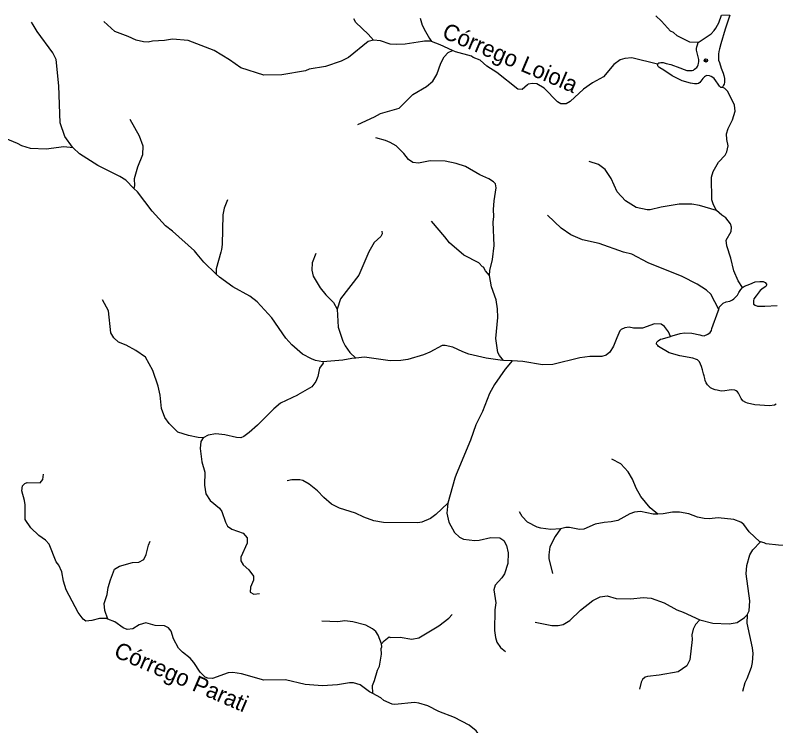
# Model space of a CAD drawing. Extents: x 317.8 to 344.1, y 7676.8 to 7704.8.
# Drawn here: x 330.394 to 334.107, y 7701.2 to 7704.671 of the extents above; entities that cross this region are included whole.
import ezdxf
from ezdxf.enums import TextEntityAlignment as Align

# ---------------------------------------------------------------- set-up
doc = ezdxf.new("R2010")
doc.units = 0
doc.header["$LTSCALE"] = 0.032
doc.header["$PDMODE"] = 32
doc.header["$PDSIZE"] = 0.016
doc.linetypes.add('SHORT_DASHED', pattern=[2.7, 1.5, -1.2])
for name, color, linetype, lineweight in [('2', 7, 'Continuous', 25), ('62', 7, 'SHORT_DASHED', 13), ('7', 7, 'Continuous', 25)]:
    doc.layers.add(name, color=color, linetype=linetype, lineweight=lineweight)
doc.layers.add('61', color=7, linetype='Continuous')

msp = doc.modelspace()

# ---------------------------------------------------------------- linework, layer by layer
at = {"layer": '2'}
for points in [[(333.7284, 7704.5377), (333.7423, 7704.5476), (333.7665, 7704.5638), (333.7907, 7704.581), (333.8053, 7704.5964), (333.8137, 7704.6085), (333.822, 7704.6227), (333.8283, 7704.6344), (333.8424, 7704.671)], [(333.8821, 7704.6714), (333.8594, 7704.6033), (333.8386, 7704.5314), (333.8311, 7704.5077), (333.8282, 7704.4945), (333.8273, 7704.4812), (333.8273, 7704.4671), (333.8273, 7704.4519), (333.8311, 7704.4406), (333.8396, 7704.4122), (333.849, 7704.3885), (333.8538, 7704.3762), (333.8556, 7704.363), (333.8566, 7704.3526), (333.8566, 7704.3441), (333.8547, 7704.3346), (333.8519, 7704.3289), (333.8468, 7704.3191)], [(333.5294, 7704.4321), (333.5308, 7704.4345), (333.5333, 7704.437), (333.5358, 7704.4387), (333.5396, 7704.4395), (333.5454, 7704.4404), (333.5567, 7704.4399), (333.5721, 7704.4362), (333.5938, 7704.4299), (333.6384, 7704.4137), (333.6601, 7704.4057), (333.6722, 7704.4016), (333.6818, 7704.4011), (333.6898, 7704.4011), (333.6981, 7704.4016), (333.7056, 7704.4036), (333.7106, 7704.4078), (333.7169, 7704.412), (333.7215, 7704.4166), (333.7252, 7704.4212), (333.7281, 7704.4287), (333.7298, 7704.4362), (333.7298, 7704.437), (333.7302, 7704.4429), (333.7302, 7704.4554), (333.7294, 7704.462), (333.724, 7704.4804), (333.7202, 7704.5004), (333.7202, 7704.5088), (333.7219, 7704.5163), (333.7252, 7704.5267), (333.7284, 7704.5377)], [(333.8468, 7704.3191), (333.8445, 7704.3181), (333.8391, 7704.3189), (333.8312, 7704.3248), (333.8249, 7704.334), (333.8141, 7704.3515), (333.8062, 7704.3623), (333.7986, 7704.3678), (333.7907, 7704.3723), (333.7828, 7704.3753), (333.7707, 7704.3761), (333.764, 7704.3744), (333.7582, 7704.3707), (333.7507, 7704.3619), (333.7407, 7704.3498), (333.7356, 7704.3431), (333.7286, 7704.3373), (333.7227, 7704.3356), (333.7156, 7704.3356), (333.7102, 7704.3365), (333.6906, 7704.3394), (333.6489, 7704.3511), (333.6013, 7704.3757), (333.56, 7704.4032), (333.5408, 7704.4137), (333.5358, 7704.4178), (333.5325, 7704.4207), (333.5316, 7704.4237), (333.5308, 7704.4274), (333.5294, 7704.4321)], [(333.9441, 7703.3415), (333.9545, 7703.3478), (333.9795, 7703.3582), (334.0066, 7703.3686), (334.0295, 7703.3707), (334.0452, 7703.3707), (334.0556, 7703.3665), (334.0618, 7703.3582), (334.0618, 7703.353), (334.0587, 7703.3457), (334.0452, 7703.3373), (334.0306, 7703.3259), (334.0108, 7703.3009), (333.9993, 7703.2863), (333.9972, 7703.2769), (333.9972, 7703.2675), (333.9983, 7703.2602), (334.0056, 7703.255), (334.017, 7703.2508), (334.0493, 7703.2508), (334.0535, 7703.2508), (334.114, 7703.2529)], [(333.8282, 7703.2344), (333.8325, 7703.2467), (333.8409, 7703.2571), (333.8502, 7703.2644), (333.8648, 7703.2706), (333.8826, 7703.2748), (333.8961, 7703.2811), (333.9024, 7703.2852), (333.9201, 7703.304), (333.9263, 7703.3175), (333.9357, 7703.3311), (333.9441, 7703.3415)], [(333.5921, 7703.1024), (333.6001, 7703.1049), (333.6397, 7703.1164), (333.6616, 7703.1195), (333.697, 7703.1174), (333.7356, 7703.1101), (333.745, 7703.107), (333.7564, 7703.1059), (333.7752, 7703.1132), (333.7867, 7703.1216), (333.7929, 7703.131), (333.794, 7703.1403), (333.8252, 7703.2258), (333.8282, 7703.2344)], [(334.1077, 7702.7714), (334.1004, 7702.7672), (334.0754, 7702.763), (334.0045, 7702.7682), (333.9691, 7702.7755), (333.9607, 7702.7797), (333.9461, 7702.788), (333.9378, 7702.7995), (333.9284, 7702.8193), (333.9253, 7702.8245), (333.9201, 7702.8318), (333.9138, 7702.837), (333.9065, 7702.8401), (333.8919, 7702.8412), (333.8784, 7702.8401), (333.8575, 7702.836), (333.8398, 7702.8349), (333.8211, 7702.8391), (333.8106, 7702.8422), (333.7981, 7702.8464), (333.7887, 7702.8516), (333.7783, 7702.861), (333.7731, 7702.8662), (333.7669, 7702.8756), (333.7616, 7702.8871), (333.7606, 7702.8964), (333.7575, 7702.91), (333.7543, 7702.9194), (333.7491, 7702.9392), (333.7439, 7702.9548), (333.7387, 7702.9663), (333.7335, 7702.9777), (333.7304, 7702.9819), (333.7252, 7702.9882), (333.72, 7702.9902), (333.7022, 7702.9955), (333.6387, 7703.0069), (333.5865, 7703.0215), (333.5344, 7703.0528), (333.5302, 7703.058), (333.5271, 7703.0611), (333.525, 7703.0642), (333.525, 7703.0684), (333.5261, 7703.0736), (333.5323, 7703.0809), (333.5438, 7703.0882), (333.5532, 7703.0903), (333.5921, 7703.1024)]]:
    msp.add_lwpolyline(points, dxfattribs=at)
msp.add_point((333.7653, 7704.4505), dxfattribs=at)
at = {"layer": '62'}
msp.add_line((333.8424, 7704.671), (333.8821, 7704.6714), dxfattribs=at)
at = {"layer": '7'}
msp.add_line((332.8198, 7702.9823), (332.7774, 7702.9849), dxfattribs=at)
for points in [[(333.7284, 7704.5377), (333.6871, 7704.539), (333.626, 7704.5709), (333.6074, 7704.5875), (333.5927, 7704.5935), (333.5487, 7704.6429), (333.5207, 7704.6678)], [(330.677, 7704.0232), (330.6729, 7704.0272), (330.6365, 7704.0793), (330.6128, 7704.145), (330.6059, 7704.3271), (330.5942, 7704.4543), (330.5777, 7704.488), (330.5009, 7704.5915), (330.4813, 7704.624), (330.4732, 7704.6374)], [(332.1422, 7704.5501), (332.1162, 7704.5432), (332.0214, 7704.4652), (331.9844, 7704.4461), (331.9088, 7704.4207), (331.8285, 7704.4073), (331.8109, 7704.3991), (331.695, 7704.3803), (331.6067, 7704.3786), (331.4945, 7704.4151), (331.4399, 7704.4539), (331.3652, 7704.4994), (331.238, 7704.5472), (331.1607, 7704.5539), (331.1217, 7704.5473), (331.0646, 7704.5449), (331.0423, 7704.5395), (331.0196, 7704.5408), (330.9847, 7704.5493), (330.9452, 7704.5675), (330.8801, 7704.592), (330.8627, 7704.6077), (330.8259, 7704.6409)], [(332.1422, 7704.5501), (332.1175, 7704.5792), (332.057, 7704.6357), (332.0473, 7704.6532)], [(332.371, 7704.6564), (332.3798, 7704.6224), (332.3964, 7704.5914), (332.4163, 7704.5573), (332.4251, 7704.5424)], [(332.4251, 7704.5424), (332.4204, 7704.5441), (332.3921, 7704.5448), (332.3822, 7704.5433), (332.2969, 7704.5302), (332.2527, 7704.5278), (332.2249, 7704.5301), (332.1777, 7704.546), (332.1422, 7704.5501)], [(332.5291, 7704.4987), (332.4684, 7704.5274), (332.4251, 7704.5424)], [(332.0657, 7704.1374), (332.1482, 7704.1742), (332.1772, 7704.1911), (332.2677, 7704.2178), (332.334, 7704.2841), (332.4021, 7704.3232), (332.4321, 7704.3498), (332.4526, 7704.3824), (332.4708, 7704.4376), (332.4874, 7704.4685), (332.5076, 7704.4896), (332.5291, 7704.4987)], [(333.5294, 7704.4321), (333.4034, 7704.4633), (333.3697, 7704.46), (333.3477, 7704.4527), (333.3153, 7704.431), (333.2655, 7704.3708), (333.212, 7704.3417), (333.1687, 7704.3109), (333.1033, 7704.2494), (333.0831, 7704.2381), (333.0576, 7704.2385), (333.0414, 7704.2486), (332.9759, 7704.3142), (332.9398, 7704.3362), (332.9182, 7704.3378), (332.8986, 7704.3347), (332.8953, 7704.3318), (332.8686, 7704.3089), (332.8475, 7704.3109), (332.7455, 7704.3913), (332.6967, 7704.4232), (332.663, 7704.4511), (332.6297, 7704.4647), (332.6206, 7704.4717), (332.5424, 7704.4924), (332.5291, 7704.4987)], [(333.8167, 7703.7178), (333.8024, 7703.7449), (333.7951, 7703.7703), (333.7934, 7703.8795), (333.8016, 7703.9075), (333.8277, 7703.9534), (333.8597, 7703.9884), (333.8684, 7704.0038), (333.8748, 7704.0334), (333.8674, 7704.0638), (333.866, 7704.0917), (333.8746, 7704.1187), (333.8956, 7704.161), (333.9083, 7704.2026), (333.9059, 7704.2319), (333.8725, 7704.2983), (333.8664, 7704.3045), (333.8583, 7704.3126), (333.8468, 7704.3191)], [(330.954, 7704.1643), (330.9986, 7704.0822), (331.0174, 7704.033), (331.0158, 7703.989), (330.9902, 7703.9293), (330.9751, 7703.8719), (330.9759, 7703.839), (330.9733, 7703.8255)], [(330.677, 7704.0232), (330.6314, 7704.0281), (330.5451, 7704.0175), (330.4685, 7704.0209), (330.4266, 7704.0327), (330.4041, 7704.0451), (330.3461, 7704.0683), (330.3313, 7704.0722), (330.2577, 7704.0916), (330.2237, 7704.1056)], [(332.7095, 7703.3999), (332.7102, 7703.4247), (332.724, 7703.4786), (332.7322, 7703.5466), (332.7265, 7703.6606), (332.7298, 7703.6876), (332.7282, 7703.722), (332.7315, 7703.7654), (332.7412, 7703.8276), (332.7378, 7703.8473), (332.7285, 7703.8574), (332.706, 7703.8729), (332.6621, 7703.8916), (332.5916, 7703.9318), (332.5467, 7703.9468), (332.4932, 7703.9581), (332.4202, 7703.9604), (332.3625, 7703.9483), (332.3352, 7703.9517), (332.3136, 7703.9668), (332.2911, 7703.9958), (332.2532, 7704.0334), (332.2245, 7704.0501), (332.2012, 7704.0595), (332.1537, 7704.0722)], [(330.9733, 7703.8255), (330.9329, 7703.8651), (330.9048, 7703.8843), (330.7966, 7703.9368), (330.7071, 7703.9939), (330.677, 7704.0232)], [(333.8167, 7703.7178), (333.7339, 7703.7412), (333.6964, 7703.7477), (333.6346, 7703.7477), (333.5476, 7703.7334), (333.4926, 7703.7201), (333.4781, 7703.7203), (333.4255, 7703.7316), (333.3726, 7703.7642), (333.3318, 7703.8081), (333.3032, 7703.8739), (333.2733, 7703.9173), (333.241, 7703.9421), (333.1953, 7703.9565)], [(331.3753, 7703.4067), (331.3141, 7703.4657), (331.2817, 7703.504), (331.2683, 7703.5198), (331.162, 7703.6171), (331.1281, 7703.6428), (331.0616, 7703.7149), (330.9906, 7703.8086), (330.9733, 7703.8255)], [(331.43, 7703.7699), (331.4133, 7703.7287), (331.4071, 7703.6965), (331.4046, 7703.5519), (331.4013, 7703.5262), (331.3981, 7703.5145), (331.3754, 7703.4322), (331.3753, 7703.4067)], [(333.9441, 7703.3415), (333.9224, 7703.3742), (333.9018, 7703.4234), (333.8869, 7703.4845), (333.8676, 7703.5444), (333.8645, 7703.5723), (333.8888, 7703.6153), (333.8904, 7703.6353), (333.8855, 7703.653), (333.8621, 7703.6822), (333.8426, 7703.6948), (333.8167, 7703.7178)], [(332.7095, 7703.3999), (332.6892, 7703.4219), (332.6802, 7703.441), (332.6748, 7703.4429), (332.6575, 7703.461), (332.5845, 7703.4986), (332.5131, 7703.5588), (332.4918, 7703.588), (332.4259, 7703.6647)], [(333.8282, 7703.2344), (333.7898, 7703.3092), (333.7687, 7703.3289), (333.7222, 7703.3575), (333.6502, 7703.3943), (333.4841, 7703.4616), (333.4041, 7703.5045), (333.3636, 7703.514), (333.2443, 7703.5556), (333.1631, 7703.5742), (333.1063, 7703.5988), (333.0593, 7703.6303), (332.9915, 7703.6949)], [(332.1839, 7703.6166), (332.1845, 7703.6028), (332.1787, 7703.5902), (332.1463, 7703.5603), (332.1204, 7703.5153), (332.0708, 7703.4008), (331.981, 7703.2867), (331.9649, 7703.2361)], [(331.8619, 7703.5074), (331.8431, 7703.4613), (331.8415, 7703.4259), (331.8475, 7703.3968), (331.8819, 7703.3404), (331.9097, 7703.3047), (331.9472, 7703.268), (331.9649, 7703.2361)], [(331.8962, 7702.9774), (331.8597, 7702.9849), (331.8394, 7702.9924), (331.7964, 7703.0157), (331.7447, 7703.0604), (331.7147, 7703.0939), (331.6458, 7703.1935), (331.5749, 7703.2709), (331.5393, 7703.2991), (331.4564, 7703.3445), (331.3905, 7703.3921), (331.3753, 7703.4067)], [(332.7774, 7702.9849), (332.7577, 7703.0086), (332.7494, 7703.0243), (332.7397, 7703.0921), (332.7493, 7703.1949), (332.7477, 7703.2363), (332.7413, 7703.2813), (332.7188, 7703.3439), (332.7095, 7703.3999)], [(331.312, 7702.6076), (331.286, 7702.6091), (331.2397, 7702.6178), (331.1883, 7702.6353), (331.1446, 7702.6768), (331.1236, 7702.7059), (331.1072, 7702.7499), (331.1013, 7702.8146), (331.0914, 7702.8601), (331.0663, 7702.9352), (331.0289, 7703.0004), (330.9824, 7703.0338), (330.9352, 7703.059), (330.8983, 7703.0747), (330.8745, 7703.0949), (330.8609, 7703.1206), (330.8495, 7703.2274), (330.8203, 7703.2808)], [(331.9649, 7703.2361), (331.9703, 7703.148), (331.9928, 7703.0785), (332.0038, 7703.0567), (332.0275, 7703.024), (332.0558, 7702.9965)], [(333.5921, 7703.1024), (333.5827, 7703.1245), (333.5627, 7703.1511), (333.5471, 7703.1622), (333.5143, 7703.1642), (333.4564, 7703.1426), (333.4119, 7703.1431), (333.391, 7703.148), (333.3695, 7703.1448), (333.3514, 7703.1368), (333.3448, 7703.129), (333.3314, 7703.096), (333.3145, 7703.0541), (333.2966, 7703.0259), (333.2785, 7703.0106), (333.2576, 7703.0048), (333.1986, 7703.0036), (333.1497, 7702.997), (333.0178, 7702.9646), (332.9675, 7702.963), (332.872, 7702.9792), (332.8198, 7702.9823)], [(332.7774, 7702.9849), (332.7617, 7702.9858), (332.6925, 7702.9958), (332.6079, 7703.0158), (332.5782, 7703.0264), (332.5296, 7703.05), (332.4929, 7703.0583), (332.4782, 7703.0579), (332.4182, 7703.0255), (332.3872, 7703.0125), (332.3104, 7702.9901), (332.2757, 7702.9842), (332.2233, 7702.9828), (332.099, 7703.0004), (332.0558, 7702.9965)], [(332.0558, 7702.9965), (332.0375, 7702.9948), (331.9938, 7702.9858), (331.8962, 7702.9774)], [(331.8962, 7702.9774), (331.8963, 7702.9717), (331.8799, 7702.9478), (331.8709, 7702.907), (331.8607, 7702.8817), (331.8415, 7702.8554), (331.7736, 7702.8166), (331.7717, 7702.8155), (331.6893, 7702.7764), (331.6562, 7702.7482), (331.5771, 7702.6693), (331.5361, 7702.633), (331.5091, 7702.6137), (331.4951, 7702.6076), (331.4737, 7702.6084), (331.4166, 7702.6221), (331.3736, 7702.6263), (331.336, 7702.6198), (331.312, 7702.6076)], [(332.8198, 7702.9823), (332.7857, 7702.9431), (332.7329, 7702.867), (332.7088, 7702.8234), (332.6751, 7702.7352), (332.6425, 7702.67), (332.616, 7702.596), (332.547, 7702.4285), (332.5392, 7702.4095), (332.505, 7702.2878)], [(331.312, 7702.6076), (331.3, 7702.5897), (331.2963, 7702.5551), (331.3045, 7702.489), (331.3198, 7702.4389), (331.3175, 7702.3758), (331.3245, 7702.3336), (331.3456, 7702.3007), (331.3902, 7702.2626), (331.4029, 7702.2466), (331.42, 7702.1943), (331.4302, 7702.1762), (331.4513, 7702.1604), (331.5064, 7702.142), (331.5266, 7702.1178), (331.5252, 7702.0918), (331.4944, 7702.0233), (331.4958, 7702.006), (331.5059, 7701.9863), (331.5336, 7701.9618), (331.5571, 7701.9316), (331.557, 7701.9124), (331.5415, 7701.8778), (331.5402, 7701.8523), (331.5583, 7701.844), (331.5864, 7701.8473)], [(333.5303, 7702.2347), (333.4938, 7702.265), (333.4478, 7702.3211), (333.4257, 7702.3607), (333.4072, 7702.4051), (333.3854, 7702.4411), (333.3498, 7702.4798), (333.3061, 7702.5033)], [(330.845, 7701.7217), (330.8393, 7701.724), (330.8055, 7701.725), (330.7675, 7701.7139), (330.7388, 7701.7108), (330.7262, 7701.7204), (330.7016, 7701.7536), (330.642, 7701.8646), (330.6295, 7701.9062), (330.6214, 7701.9528), (330.6067, 7701.9849), (330.5931, 7702.0015), (330.5596, 7702.0881), (330.5419, 7702.1075), (330.5086, 7702.1305), (330.4702, 7702.1671), (330.4425, 7702.2075), (330.4428, 7702.2749), (330.4422, 7702.2797), (330.4396, 7702.3003), (330.4258, 7702.3477), (330.4294, 7702.3725), (330.4413, 7702.3842), (330.4519, 7702.3893), (330.5152, 7702.3872), (330.5286, 7702.4036), (330.531, 7702.43)], [(332.505, 7702.2878), (332.4468, 7702.2324), (332.4212, 7702.2136), (332.3786, 7702.1955), (332.3585, 7702.1911), (332.1916, 7702.1928), (332.1447, 7702.2009), (332.0953, 7702.2195), (332.055, 7702.2392), (331.9775, 7702.2638), (331.9385, 7702.2832), (331.8999, 7702.3152), (331.8691, 7702.3482), (331.8279, 7702.3805), (331.7977, 7702.398), (331.7828, 7702.4021), (331.7439, 7702.4022), (331.7217, 7702.3974)], [(332.505, 7702.2878), (332.5, 7702.2385), (332.511, 7702.1954), (332.5385, 7702.1448), (332.5629, 7702.1223), (332.5814, 7702.1125), (332.6374, 7702.1048), (332.6583, 7702.1064), (332.7151, 7702.1193), (332.7601, 7702.1178), (332.7787, 7702.1047), (332.7916, 7702.0805), (332.8, 7702.0447), (332.7984, 7701.9938), (332.7819, 7701.9433), (332.7693, 7701.9232), (332.7366, 7701.8866), (332.7298, 7701.8646), (332.7395, 7701.8014), (332.7356, 7701.7669), (332.7339, 7701.6658), (332.738, 7701.6317), (332.745, 7701.6083), (332.7626, 7701.5824), (332.7878, 7701.5628)], [(333.5303, 7702.2347), (333.5082, 7702.2342), (333.4463, 7702.2473), (333.4165, 7702.2433), (333.394, 7702.2362), (333.3355, 7702.2039), (333.3024, 7702.196), (333.2681, 7702.1936), (333.2241, 7702.185), (333.1688, 7702.1615), (333.1484, 7702.1585), (333.1003, 7702.1683), (333.0812, 7702.1681), (333.0562, 7702.1619)], [(333.0562, 7702.1619), (333.0078, 7702.1585), (332.9593, 7702.1652), (332.9422, 7702.1708), (332.9414, 7702.1712), (332.8947, 7702.1956), (332.8691, 7702.2221), (332.8554, 7702.2458)], [(334.0315, 7702.0991), (334.0295, 7702.0997), (333.9774, 7702.1472), (333.9514, 7702.1837), (333.9363, 7702.1957), (333.9018, 7702.2073), (333.826, 7702.2155), (333.7808, 7702.2107), (333.7571, 7702.2122), (333.7241, 7702.2196), (333.6814, 7702.2352), (333.6365, 7702.2432), (333.6032, 7702.2432), (333.5567, 7702.2354), (333.5303, 7702.2347)], [(333.0562, 7702.1619), (333.0291, 7702.1255), (333.0035, 7702.0743), (332.9988, 7702.0357), (332.9995, 7702.0167), (333.0168, 7701.9442)], [(330.845, 7701.7217), (330.8305, 7701.763), (330.8284, 7701.7983), (330.8426, 7701.8424), (330.8479, 7701.8765), (330.8581, 7701.9135), (330.8789, 7701.965), (330.9023, 7701.9807), (330.9661, 7701.9987), (330.9973, 7702.0002), (331.0223, 7702.0127), (331.0334, 7702.037), (331.0443, 7702.0832), (331.0526, 7702.1023)], [(333.9672, 7701.7428), (333.977, 7701.7613), (333.98, 7701.8105), (333.9625, 7701.9428), (333.9646, 7701.9828), (333.9799, 7702.0359), (333.9948, 7702.0602), (334.0315, 7702.0991)], [(334.5476, 7702.0136), (334.462, 7702.0213), (334.3546, 7702.0542), (334.3049, 7702.0627), (334.2614, 7702.0805), (334.2331, 7702.0867), (334.2031, 7702.0867), (334.1566, 7702.0811), (334.1195, 7702.0819), (334.0604, 7702.0898), (334.0494, 7702.0933), (334.0315, 7702.0991)], [(332.9312, 7701.7062), (333.0131, 7701.6899), (333.044, 7701.6902), (333.0679, 7701.695), (333.1017, 7701.7145), (333.1527, 7701.7644), (333.2134, 7701.8131), (333.2495, 7701.8299), (333.2835, 7701.835), (333.3274, 7701.8229), (333.3998, 7701.8211), (333.459, 7701.8268), (333.4982, 7701.823), (333.5624, 7701.8008), (333.623, 7701.7672), (333.6543, 7701.7557), (333.7353, 7701.7171)], [(332.1824, 7701.6006), (332.1943, 7701.6156), (332.2189, 7701.6342), (332.2256, 7701.6321), (332.2734, 7701.6336), (332.3294, 7701.6239), (332.3637, 7701.6299), (332.4611, 7701.6878), (332.5109, 7701.7268), (332.5262, 7701.7437)], [(333.7353, 7701.7171), (333.7988, 7701.7021), (333.8795, 7701.6976), (333.9174, 7701.7051), (333.9534, 7701.7285), (333.9672, 7701.7428)], [(333.9672, 7701.7428), (333.9655, 7701.7014), (333.9914, 7701.5815), (333.9939, 7701.5541), (333.9914, 7701.5098), (333.9865, 7701.4853), (333.9656, 7701.4289), (333.9556, 7701.4103), (333.9443, 7701.3672)], [(330.9205, 7701.6793), (330.8796, 7701.7075), (330.845, 7701.7217)], [(332.1388, 7701.3581), (332.1239, 7701.3663), (332.0778, 7701.3997), (332.0446, 7701.4102), (332.0257, 7701.4103), (331.9675, 7701.4004), (331.8943, 7701.3949), (331.8089, 7701.4026), (331.7134, 7701.4249), (331.6081, 7701.4226), (331.4984, 7701.4537), (331.4559, 7701.46), (331.4339, 7701.4583), (331.356, 7701.4316), (331.3332, 7701.4332), (331.321, 7701.4385), (331.2971, 7701.4615), (331.265, 7701.51), (331.2473, 7701.5309), (331.2101, 7701.5592), (331.1903, 7701.5793), (331.1668, 7701.6252), (331.1543, 7701.6621), (331.1423, 7701.6781), (331.1227, 7701.689), (331.0767, 7701.6907), (331.0313, 7701.7037), (330.9986, 7701.6938), (330.9674, 7701.6739), (330.94, 7701.6712), (330.9205, 7701.6793)], [(332.1824, 7701.6006), (332.1658, 7701.643), (332.1538, 7701.6602), (332.1376, 7701.6742), (332.1052, 7701.6916), (332.0425, 7701.7085), (332.0022, 7701.7134), (331.9693, 7701.7078), (331.8913, 7701.712)], [(333.7353, 7701.7171), (333.7151, 7701.6956), (333.7027, 7701.672), (333.6965, 7701.6438), (333.698, 7701.6226), (333.6866, 7701.5228), (333.6716, 7701.4924), (333.6308, 7701.4644), (333.5374, 7701.447), (333.4797, 7701.4414), (333.4687, 7701.4375), (333.4561, 7701.4266), (333.4487, 7701.414), (333.4406, 7701.3786)], [(332.1388, 7701.3581), (332.1381, 7701.397), (332.1483, 7701.4213), (332.1625, 7701.4722), (332.1723, 7701.4908), (332.1813, 7701.5498), (332.1798, 7701.5785), (332.1828, 7701.5859), (332.1824, 7701.6006)], [(332.7127, 7701.0636), (332.7039, 7701.0855), (332.6788, 7701.1305), (332.6437, 7701.1753), (332.6105, 7701.2027), (332.5375, 7701.2407), (332.4622, 7701.2695), (332.4081, 7701.2981), (332.3644, 7701.3109), (332.3427, 7701.3133), (332.2463, 7701.3044), (332.2335, 7701.3067), (332.1926, 7701.3243), (332.1788, 7701.3361), (332.1388, 7701.3581)]]:
    msp.add_lwpolyline(points, dxfattribs=at)

# ---------------------------------------------------------------- texts
at = {"layer": '61'}
for s, rotation, p in [('Córrego Loiola', 337.036, (332.7951, 7704.4266)), ('Córrego Parati', 336.736, (331.1893, 7701.4022))]:
    msp.add_text(s, height=0.08, rotation=rotation, dxfattribs=at).set_placement(p, align=Align.CENTER)

doc.saveas('drawing.dxf')
